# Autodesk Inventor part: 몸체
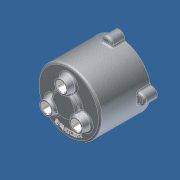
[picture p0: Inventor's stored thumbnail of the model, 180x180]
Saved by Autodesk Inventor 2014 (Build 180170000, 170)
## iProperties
Created: 2012-05
Part Number: 몸체
Document SubType Name: 모델링
Designer: SeoGD™
Material: 알루미늄 6061
Appearance: 알루미늄 - 평지
Mass: 475.553 g
Surface Area: 687.661 cm^2
Volume: 175.481 cm^3
Density: 2.71 g/cm^3
변환 표준: STEP AP214IS
파일 이름: C:\Users\SeoGD\Desktop\?쒗뿕\紐몄껜.stp
전처리기: Build: 253, Release: 2010 SP1 - Date: Wed 07/29/2009
전송 단위: 밀리미터
불확실성: 0.01
Author: SeoGD™
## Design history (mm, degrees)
sketch "스케치2"
  geometry: C1 r 50 at (0, 0); 1 further point
  constraints: 1 centre point, 1 coincident
  dimensions: "d9" = 100 diameter of C1
extrude "돌출2" new body sketch "스케치2" distance "d10" = 80; taper "d11" = 0 deg
feature "쉘1" dims "d12" = 5
sketch "스케치3" dims "d13" = 55
  geometry: C1 r 7.5 at (0, 27.5); C2 r 12.5 at (0, 27.5); 2 further points
  constraints: 2 centre point, 2 coincident, 2 vertical alignment, 2 other
  dimensions: "d14" = 15 diameter of C1; "d15" = 25 diameter of C2
extrude "돌출3" join sketch "스케치3" distance "d16" = 12; taper "d17" = -10 deg
hole "구멍2" diameter "d20" = 15; stored, may be unused: countersink angle "d24" = 90 deg, drill point angle "d26" = 118 deg; dims "d18" = 10, "d19" = 10, "d21" = 6, "d22" = 4, "d23" = 2, "d25" = 15
chamfer "모따기1" distance "d27" = 1; stored, may be unused: second distance "d28" = 2, angle "d29" = 45 deg
sketch "스케치4"
  geometry: L1 (0, 0)-(0, 88); L2 (0, 70)-(13.16, 70); L3 (-45, 75)-(45, 75) reference; L4 (-50, 80)-(50, 80) reference; L5 (13.16, 70)-(14.5, 75); L6 (20, 80)-(20, 88); L7 (20, 88)-(0, 88); L8 (20, 80)-(14.5, 75)
  constraints: 12 end point, 3 point on line, 2 perpendicular, 1 vertical
  dimensions: "d34" = 40 diameter of L6 L1; "d35" = 105 deg angle of L5 L3; "d36" = 5 distance between parallel lines of L2 L3; "d37" = 8 distance between parallel lines of L7 L4; "d51" = 29 diameter of L5.end L1
revolve "회전1" sketch "스케치4" stored, may be unused: angle "d38" = 90 deg
hole "구멍3" diameter "d41" = 15; stored, may be unused: countersink angle "d45" = 90 deg, drill point angle "d47" = 0 deg; dims "d39" = 10, "d40" = 10, "d42" = 6, "d43" = 22, "d44" = 13, "d46" = 15
chamfer "모따기2" distance "d48" = 1; stored, may be unused: second distance "d49" = 2, angle "d50" = 45 deg
fillet "모깎기1" dims "d52" = 3
fillet "모깎기2" dims "d53" = 3, "d72" = 0.2
sketch "스케치5"
  geometry: A1 r 50 centre (0, 0) between (50, 0) and (-8.074, 49.344) reference; A2 r 8.5 centre (0, 52) between (8.074, 49.344) and (-8.074, 49.344); 1 further point
  constraints: 5 point on circle, 1 centre point, 1 horizontal alignment
  dimensions: "d54" = 90 deg dimension on point (0, 0) A2.centre A1.start; "d55" = 52 distance of A2.centre point (0, 0); "d56" = 17 diameter of A2
extrude "돌출4" join sketch "스케치5" distance "d57" = 20; taper "d58" = 0 deg
fillet "모깎기3" dims "d59" = 3
hole "구멍4" diameter "d62" = 4.134; stored, may be unused: countersink angle "d66" = 90 deg, drill point angle "d68" = 118 deg; dims "d60" = 10, "d61" = 10, "d63" = 12, "d64" = 22, "d65" = 13, "d67" = 15
sketch "스케치6"
  geometry: C1 r 47 at (0, 0) reference; C2 r 42.5 at (0, 0); 1 further point
  constraints: 1 centre point, 1 coincident, 1 other
  dimensions: "d73" = 85 diameter of C2
feature "엠보싱1" sketch "스케치6" dims "d74" = 1, "d75" = 0
node "솔리드1"
node "솔리드 본체"
node "곡면 본체"
pattern_circular "원형 패턴1" dims "d31" = 360 deg
pattern_circular "원형 패턴2" dims "d70" = 360 deg
node "솔리드2"
